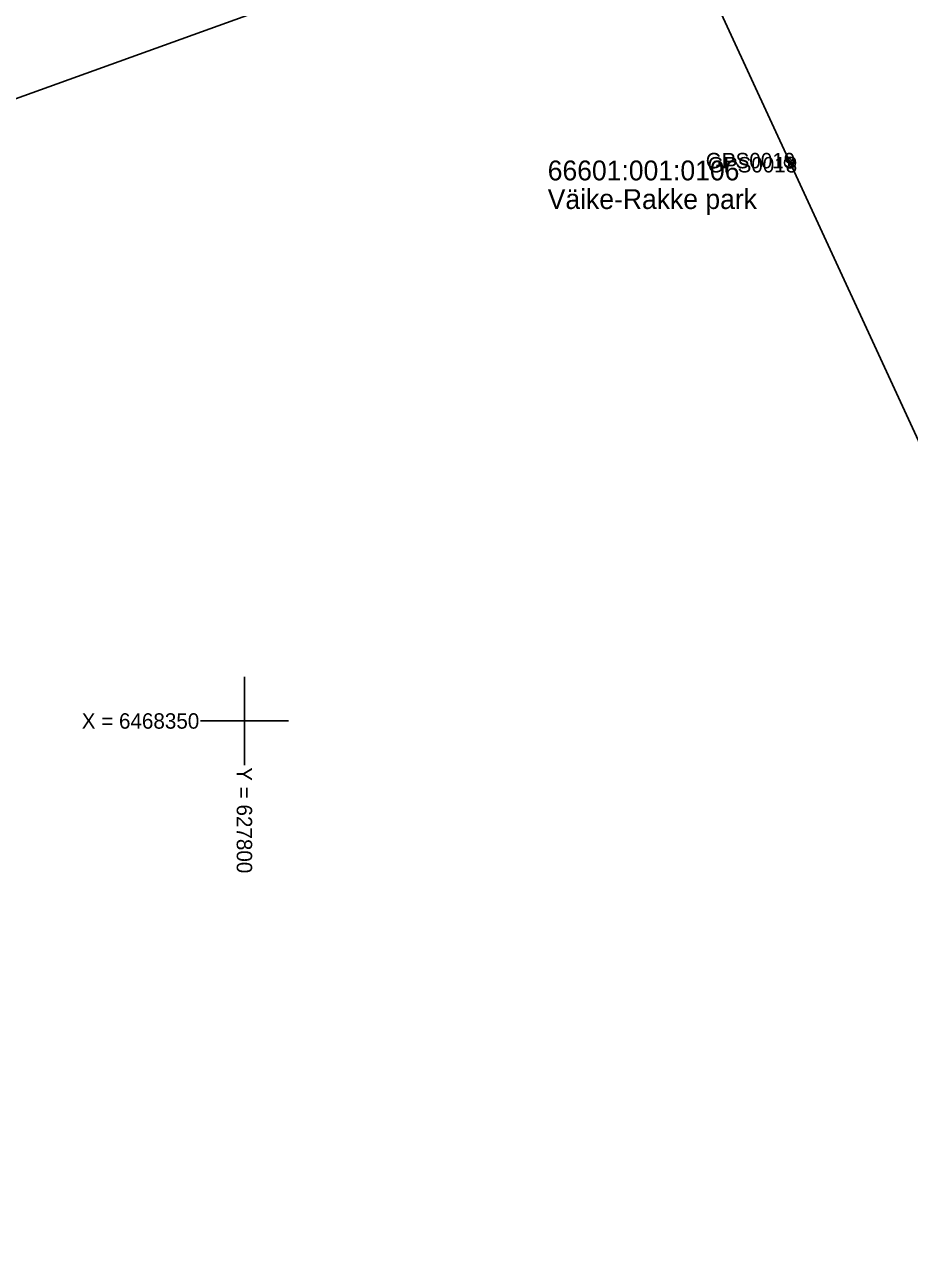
# Model space of a CAD drawing. Extents: x 626224 to 628280, y 6467750 to 6471135.
# Drawn here: x 627790 to 627830.2, y 6468325.8 to 6468381.6 of the extents above; entities that cross this region are included whole.
import ezdxf

# ---------------------------------------------------------------- set-up
doc = ezdxf.new("R2010")
doc.units = 0
for name, color, linetype in [('MOOTMPUNKT', 7, 'Continuous'), ('MOOTNR', 7, 'Continuous'), ('MPOHULIIN', 7, 'Continuous'), ('PIIR', 7, 'Continuous'), ('POST', 7, 'Continuous'), ('VORK', 7, 'Continuous')]:
    doc.layers.add(name, color=color, linetype=linetype)

msp = doc.modelspace()

# ---------------------------------------------------------------- linework, layer by layer
at = {"layer": 'MOOTMPUNKT'}
for centre in [(627824.722, 6468375.437), (627824.812, 6468375.249)]:
    msp.add_circle(centre, 0.1, dxfattribs=at)
at = {"layer": 'MPOHULIIN'}
msp.add_lwpolyline([(627835.693, 6468351.671), (627824.767, 6468375.343), (627808.334, 6468410.91), (627776.772, 6468462.547)], dxfattribs=at)
at = {"layer": 'PIIR'}
for points in [[(627802, 6468382.71), (627775.07, 6468451.79), (627801.28, 6468461.34), (627809.58, 6468448), (627816.81, 6468434.6), (627826.02, 6468416.53), (627834.21, 6468400.21), (627843.3, 6468381.02), (627850.92, 6468363.47), (627860.61, 6468341.12), (627869.05, 6468319.44), (627817.44, 6468300.95), (627762.12, 6468283.97), (627745.3, 6468323.41), (627778.35, 6468337.62), (627766.32, 6468369.86)], [(627775.07, 6468451.79), (627802, 6468382.71), (627766.32, 6468369.86), (627762.49, 6468377.13), (627743.21, 6468369.09), (627733.67, 6468392.46), (627728.72, 6468407.08), (627739.62, 6468413.09), (627729.69, 6468435.15)]]:
    msp.add_lwpolyline(points, close=True, dxfattribs=at)
at = {"layer": 'POST'}
for radius in [0.25, 0.0234]:
    msp.add_circle((627824.767, 6468375.343), radius, dxfattribs=at)
at = {"layer": 'VORK'}
for p, q in [((627800, 6468352), (627800, 6468348)), ((627798, 6468350), (627802, 6468350))]:
    msp.add_line(p, q, dxfattribs=at)

# ---------------------------------------------------------------- texts
at = {"layer": 'MOOTNR'}
for s, p in [('GPS0019 ', (627820.942, 6468375.087)), ('GPS0018 ', (627821.033, 6468374.899))]:
    msp.add_text(s, height=0.7, dxfattribs=at).set_placement(p)
at = {"layer": 'PIIR'}
for s, p in [('66601:001:0106', (627813.768, 6468374.54)), ('Väike-Rakke park', (627813.768, 6468373.24))]:
    msp.add_text(s, height=0.9, dxfattribs=at).set_placement(p)
at = {"layer": 'VORK'}
msp.add_text('X = 6468350', height=0.7, dxfattribs=at).set_placement((627792.615, 6468349.65))
msp.add_text('Y = 627800 ', height=0.7, rotation=270, dxfattribs=at).set_placement((627799.65, 6468347.9))

doc.saveas('drawing.dxf')
